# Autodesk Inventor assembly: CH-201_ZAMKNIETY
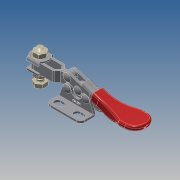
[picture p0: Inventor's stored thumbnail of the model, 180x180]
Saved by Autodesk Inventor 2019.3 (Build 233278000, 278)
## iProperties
Company: Î¢ÈíÖÐ¹ú
Created: 2012-09
Part Number: CH-201_ZAMKNIETY
Material: Ogólny
Description: STEP AP203
Document SubType Name: Assembly
Designer: CADENGINEERING4
Sending System: SolidWorks 2010
Preprocessor: SwSTEP 2.0
Title: CH-201.STEP
Author: Î¢ÈíÓÃ»§
Revision Number: ÈÎºÎ
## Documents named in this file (9)
- E:\STRONA\Horizontal toggle clamp\CH-201\CH-201_ZAMKNIETY.iam
- E:\STRONA\Horizontal toggle clamp\CH-201\CH-201-02 U-BAR.ipt
- E:\STRONA\Horizontal toggle clamp\CH-201\CH-FW-080.ipt
- E:\STRONA\Horizontal toggle clamp\CH-201\CH-201-A-06.ipt
- E:\STRONA\Horizontal toggle clamp\CH-201\CH-201-A-04.ipt
- E:\STRONA\Horizontal toggle clamp\CH-201\CH-201-03 HANDLE.iam
- E:\STRONA\Horizontal toggle clamp\CH-201\M4 Nut.ipt
- E:\STRONA\Horizontal toggle clamp\CH-201\CH-SA-042007 SPINDLE SUPPLIED.ipt
- E:\STRONA\Horizontal toggle clamp\CH-201\CH-201-01 FLANGED BASE.ipt
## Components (14 placed, 14 different names)
1. CH-201-02 U-BAR_1 — Zestawiające:23, Zestawiające:24, Zestawiające:25, Zestawiające:26, Równoległe:3, Zestawiające:27, Zestawiające:28
2. CH-FW-080_2 — Zestawiające:20, Zestawiające:21, Zestawiające:24, Równoległe:2
3. CH-201-A-06_3 — Zestawiające:6, Zestawiające:12
4. CH-201-A-04_4 — Zestawiające:1, Zestawiające:2, Zestawiające:3, Zestawiające:9, Zestawiające:10, Zestawiające:11
5. CH-201-03 HANDLE_5 [sub-assembly] — Zestawiające:6, Zestawiające:10, Zestawiające:11, Zestawiające:13, Zestawiające:14, Przejściowe:1
6. M4 Nut_6 — Zestawiające:17, Zestawiające:21
7. CH-SA-042007 SPINDLE SUPPLIED_7 — Zestawiające:17, Równoległe:1, Zestawiające:18, Zestawiające:19, Zestawiające:20, Zestawiające:27
8. CH-201-01 FLANGED BASE_8 — Zestawiające:4, Zestawiające:5, Zestawiające:8, Zestawiające:15, Zestawiające:16, Zestawiające:26, Przejściowe:1
9. M4 Nut_9 — Równoległe:1, Zestawiające:18, Zestawiające:22
10. CH-201-A-04_10 — Zestawiające:1, Zestawiające:2, Zestawiające:3, Zestawiające:8, Zestawiające:12
11. CH-201-A-06_11 — Zestawiające:4, Zestawiające:5, Zestawiające:9
12. CH-201-A-06_12 — Zestawiające:15, Zestawiające:16, Zestawiające:25
13. CH-FW-080_13 — Zestawiające:19, Zestawiające:22, Zestawiające:23, Równoległe:2, Równoległe:3
14. CH-201-A-06_14 — Zestawiające:13, Zestawiające:14, Zestawiające:28
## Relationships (31: Mate 27, Flush 3, Transitional 1)
- Zestawiające:1 [Mate]: CH-201-A-04_4 ↔ CH-201-A-04_10
- Zestawiające:2 [Mate]: CH-201-A-04_4 ↔ CH-201-A-04_10
- Zestawiające:3 [Mate]: CH-201-A-04_4 ↔ CH-201-A-04_10
- Zestawiające:4 [Mate]: CH-201-01 FLANGED BASE_8 ↔ CH-201-A-06_11
- Zestawiające:5 [Mate]: CH-201-01 FLANGED BASE_8 ↔ CH-201-A-06_11
- Zestawiające:6 [Mate]: CH-201-A-06_3 ↔ CH-201-03 HANDLE_5
- Zestawiające:8 [Mate]: CH-201-01 FLANGED BASE_8 ↔ CH-201-A-04_10
- Zestawiające:9 [Mate]: CH-201-A-04_4 ↔ CH-201-A-06_11
- Zestawiające:10 [Mate]: CH-201-A-04_4 ↔ CH-201-03 HANDLE_5
- Zestawiające:11 [Mate]: CH-201-A-04_4 ↔ CH-201-03 HANDLE_5
- Zestawiające:12 [Mate]: CH-201-A-06_3 ↔ CH-201-A-04_10
- Zestawiające:13 [Mate]: CH-201-03 HANDLE_5 ↔ CH-201-A-06_14
- Zestawiające:14 [Mate]: CH-201-03 HANDLE_5 ↔ CH-201-A-06_14
- Zestawiające:15 [Mate]: CH-201-01 FLANGED BASE_8 ↔ CH-201-A-06_12
- Zestawiające:16 [Mate]: CH-201-01 FLANGED BASE_8 ↔ CH-201-A-06_12
- Zestawiające:17 [Mate]: M4 Nut_6 ↔ CH-SA-042007 SPINDLE SUPPLIED_7
- Równoległe:1 [Flush]: CH-SA-042007 SPINDLE SUPPLIED_7 ↔ M4 Nut_9
- Zestawiające:18 [Mate]: CH-SA-042007 SPINDLE SUPPLIED_7 ↔ M4 Nut_9
- Zestawiające:19 [Mate]: CH-SA-042007 SPINDLE SUPPLIED_7 ↔ CH-FW-080_13
- Zestawiające:20 [Mate]: CH-FW-080_2 ↔ CH-SA-042007 SPINDLE SUPPLIED_7
- Zestawiające:21 [Mate]: CH-FW-080_2 ↔ M4 Nut_6
- Zestawiające:22 [Mate]: M4 Nut_9 ↔ CH-FW-080_13
- Zestawiające:23 [Mate]: CH-201-02 U-BAR_1 ↔ CH-FW-080_13
- Zestawiające:24 [Mate]: CH-201-02 U-BAR_1 ↔ CH-FW-080_2
- Równoległe:2 [Flush]: CH-FW-080_2 ↔ CH-FW-080_13
- Zestawiające:25 [Mate]: CH-201-02 U-BAR_1 ↔ CH-201-A-06_12
- Zestawiające:26 [Mate]: CH-201-02 U-BAR_1 ↔ CH-201-01 FLANGED BASE_8
- Równoległe:3 [Flush]: CH-201-02 U-BAR_1 ↔ CH-FW-080_13
- Zestawiające:27 [Mate]: CH-201-02 U-BAR_1 ↔ CH-SA-042007 SPINDLE SUPPLIED_7
- Zestawiające:28 [Mate]: CH-201-02 U-BAR_1 ↔ CH-201-A-06_14
- Przejściowe:1 [Transitional]: CH-201-03 HANDLE_5 ↔ CH-201-01 FLANGED BASE_8
